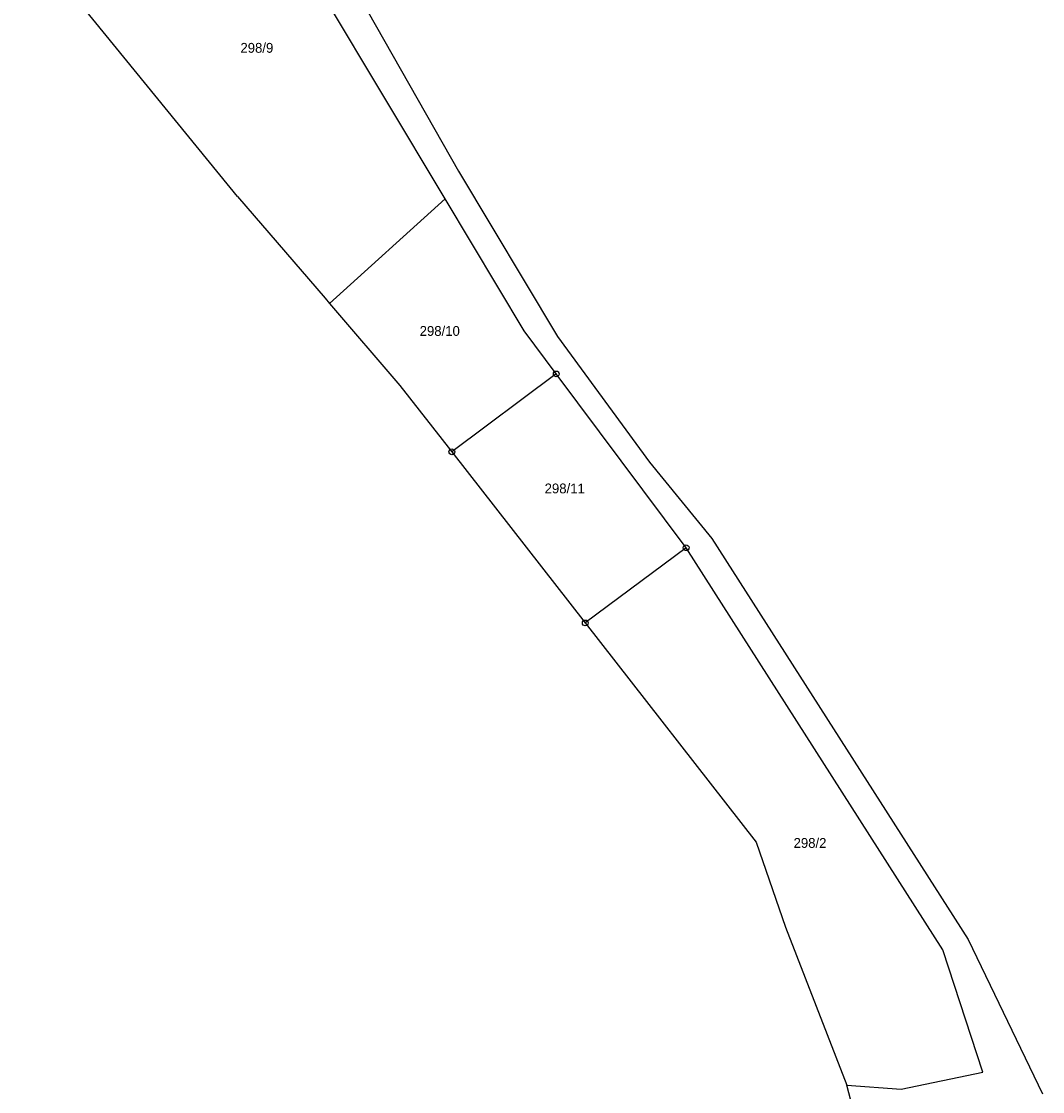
# Model space of a CAD drawing. Extents: x -794142 to -791199, y -1109267 to -1105626.
# Drawn here: x -793005 to -792828.4, y -1105989.3 to -1105804.1 of the extents above; entities that cross this region are included whole.
import ezdxf

# ---------------------------------------------------------------- set-up
doc = ezdxf.new("R2010")
doc.units = 0
for name, color, linetype in [('Vrstva 1', 7, 'Continuous'), ('Vrstva 14', 7, 'Continuous'), ('Vrstva 28', 7, 'Continuous'), ('Vrstva 4', 7, 'Continuous')]:
    doc.layers.add(name, color=color, linetype=linetype)

msp = doc.modelspace()

# ---------------------------------------------------------------- linework, layer by layer
at = {"layer": 'Vrstva 1'}
for p, q in [((-792952.8, -1105788.77), (-792929.42, -1105830)), ((-792931.74, -1105834.78), (-792957.25, -1105792.14)), ((-792929.42, -1105830), (-792912.28, -1105858.57)), ((-792951.72, -1105852.89), (-792931.74, -1105834.78)), ((-792918.08, -1105857.6), (-792931.74, -1105834.78)), ((-792912.5, -1105865.07), (-792918.08, -1105857.6)), ((-792912.28, -1105858.57), (-792896.38, -1105880.33)), ((-792912.5, -1105865.07), (-792930.57, -1105878.56)), ((-792890.04, -1105895.15), (-792912.5, -1105865.07)), ((-792896.38, -1105880.33), (-792885.57, -1105893.57)), ((-792890.04, -1105895.15), (-792907.48, -1105908.17)), ((-792845.62, -1105964.71), (-792890.04, -1105895.15)), ((-792885.57, -1105893.57), (-792841.24, -1105962.94)), ((-792841.24, -1105962.94), (-792828.39, -1105989.66)), ((-792838.72, -1105985.87), (-792845.62, -1105964.71)), ((-792852.85, -1105988.85), (-792838.72, -1105985.87)), ((-792862.27, -1105988.16), (-792852.85, -1105988.85))]:
    msp.add_line(p, q, dxfattribs=at)
at = {"layer": 'Vrstva 28'}
for centre, radius in [((-792912.5, -1105865.07), 0.5), ((-792912.5, -1105865.07), 0.01), ((-792930.57, -1105878.56), 0.5), ((-792930.57, -1105878.56), 0.01), ((-792890.04, -1105895.15), 0.5), ((-792890.04, -1105895.15), 0.01), ((-792907.48, -1105908.17), 0.5), ((-792907.48, -1105908.17), 0.01)]:
    msp.add_circle(centre, radius, dxfattribs=at)
at = {"layer": 'Vrstva 4'}
for p, q in [((-792967.63, -1105834.37), (-793005.01, -1105788.46)), ((-792967.63, -1105834.37), (-792952.49, -1105851.99)), ((-792952.49, -1105851.99), (-792951.72, -1105852.89)), ((-792951.72, -1105852.89), (-792939.54, -1105867.05)), ((-792939.54, -1105867.05), (-792930.57, -1105878.56)), ((-792930.57, -1105878.56), (-792907.48, -1105908.17)), ((-792907.48, -1105908.17), (-792877.9, -1105946.11)), ((-792877.9, -1105946.11), (-792872.88, -1105960.82)), ((-792872.88, -1105960.82), (-792862.27, -1105988.16)), ((-792860.22, -1105995.69), (-792862.27, -1105988.16))]:
    msp.add_line(p, q, dxfattribs=at)

# ---------------------------------------------------------------- texts
at = {"layer": 'Vrstva 14'}
for s, p in [('298/9', (-792967.13, -1105809.5)), ('298/10', (-792936.132, -1105858.49)), ('298/11', (-792914.516, -1105885.74)), ('298/2', (-792871.459, -1105947.08))]:
    msp.add_text(s, height=1.7, dxfattribs=at).set_placement(p)

doc.saveas('drawing.dxf')
